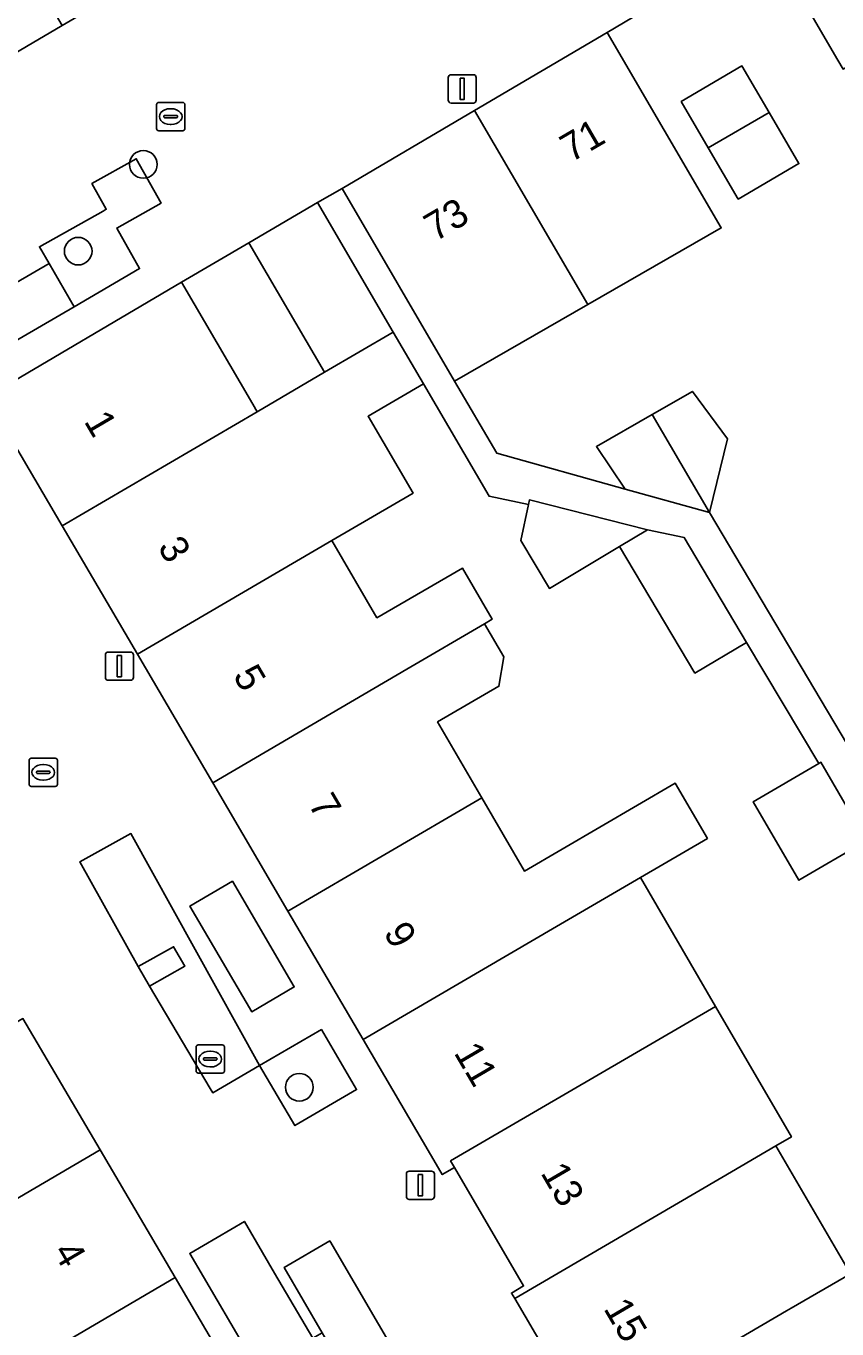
# Model space of a CAD drawing. Extents: x 161771 to 163125, y 382475 to 383179.
# Drawn here: x 162254.94 to 162283.63, y 382779.88 to 382825.98 of the extents above; entities that cross this region are included whole.
import ezdxf

# ---------------------------------------------------------------- set-up
doc = ezdxf.new("R2010")
doc.units = 0
for name, color, linetype in [('IMGEO_Boom', 7, 'Continuous'), ('IMGEO_Erf', 7, 'Continuous'), ('IMGEO_Groenvoorziening', 7, 'Continuous'), ('IMGEO_Kolk', 7, 'Continuous'), ('IMGEO_Lichtmast', 7, 'Continuous'), ('IMGEO_Muur', 7, 'Continuous'), ('IMGEO_Pand', 7, 'Continuous'), ('IMGEO_Pand_nummerreeks', 7, 'Continuous'), ('IMGEO_Parkeervlak_open', 7, 'Continuous'), ('IMGEO_Verkeerseiland_open', 7, 'Continuous'), ('IMGEO_Voetpad_open', 7, 'Continuous'), ('IMGEO_Woonerf_open', 7, 'Continuous')]:
    doc.layers.add(name, color=color, linetype=linetype)

msp = doc.modelspace()

# ---------------------------------------------------------------- linework, layer by layer
at = {"layer": 'IMGEO_Boom'}
for centre in [(162259.087, 382821.081), (162256.783, 382818.012), (162264.61, 382788.43)]:
    msp.add_circle(centre, 0.489, dxfattribs=at)
at = {"layer": 'IMGEO_Erf'}
for points in [[(162283.67, 382824.766), (162281.151, 382829.084), (162276.402, 382826.283), (162275.498, 382825.75), (162279.54, 382818.834), (162274.818, 382816.121), (162270.105, 382813.413), (162271.595, 382810.864), (162276.134, 382809.597), (162275.123, 382811.095), (162277.094, 382812.228), (162278.52, 382813.048), (162279.761, 382811.371), (162279.118, 382808.764), (162300.444, 382772.865)], [(162284.629, 382797.122), (162282.285, 382795.757), (162280.669, 382798.533), (162282.987, 382799.882), (162280.436, 382804.169), (162278.608, 382803.082), (162275.942, 382807.561), (162273.456, 382806.081), (162272.446, 382807.776), (162272.714, 382809.046), (162271.326, 382809.34), (162269.002, 382813.315), (162267.044, 382812.17), (162268.632, 382809.455), (162265.763, 382807.777), (162267.356, 382805.041), (162270.378, 382806.8), (162271.432, 382804.989), (162271.161, 382804.831), (162271.848, 382803.657), (162271.673, 382802.619), (162269.501, 382801.355), (162271.064, 382798.67), (162272.574, 382796.076), (162277.914, 382799.185), (162279.048, 382797.237), (162276.678, 382795.851), (162279.331, 382791.293), (162282.022, 382786.671), (162281.476, 382786.353), (162284.107, 382781.832)]]:
    msp.add_lwpolyline(points, dxfattribs=at)
for points in [[(162280.139, 382819.854), (162279.079, 382821.667), (162278.121, 382823.307), (162280.271, 382824.564), (162281.23, 382822.922), (162282.289, 382821.111)], [(162260.443, 382816.917), (162262.958, 382812.596), (162263.113, 382812.329), (162265.503, 382813.727), (162262.824, 382818.309)]]:
    msp.add_lwpolyline(points, close=True, dxfattribs=at)
at = {"layer": 'IMGEO_Groenvoorziening'}
for points in [[(162258.9, 382792.705), (162259.311, 382792.011), (162260.56, 382792.72), (162260.159, 382793.403)], [(162264.451, 382787.076), (162266.633, 382788.345), (162265.391, 382790.473), (162263.199, 382789.196)]]:
    msp.add_lwpolyline(points, close=True, dxfattribs=at)
at = {"layer": 'IMGEO_Kolk'}
for p, q in [((162259.558, 382822.347), (162259.558, 382823.199)), ((162259.633, 382823.273), (162260.485, 382823.273)), ((162260.559, 382823.199), (162260.559, 382822.347)), ((162259.817, 382822.767), (162259.817, 382822.779)), ((162260.255, 382822.73), (162259.857, 382822.73)), ((162259.86, 382822.816), (162260.258, 382822.816)), ((162260.046, 382823.053), (162260.071, 382823.053)), ((162260.301, 382822.779), (162260.301, 382822.767)), ((162260.485, 382822.273), (162259.633, 382822.273)), ((162260.069, 382822.493), (162260.044, 382822.493)), ((162255.121, 382800.072), (162255.973, 382800.072)), ((162255.046, 382799.146), (162255.046, 382799.998)), ((162255.305, 382799.566), (162255.305, 382799.578)), ((162255.348, 382799.615), (162255.746, 382799.615)), ((162255.534, 382799.852), (162255.559, 382799.852)), ((162255.789, 382799.578), (162255.789, 382799.566)), ((162256.047, 382799.998), (162256.047, 382799.146)), ((162255.743, 382799.529), (162255.345, 382799.529)), ((162255.557, 382799.292), (162255.532, 382799.292)), ((162255.973, 382799.072), (162255.121, 382799.072)), ((162261.031, 382789.929), (162261.883, 382789.929)), ((162260.956, 382789.003), (162260.956, 382789.855)), ((162261.215, 382789.423), (162261.215, 382789.435)), ((162261.258, 382789.472), (162261.656, 382789.472)), ((162261.444, 382789.709), (162261.469, 382789.709)), ((162261.699, 382789.435), (162261.699, 382789.423)), ((162261.957, 382789.855), (162261.957, 382789.003)), ((162261.653, 382789.386), (162261.255, 382789.386)), ((162261.467, 382789.149), (162261.442, 382789.149)), ((162261.883, 382788.929), (162261.031, 382788.929))]:
    msp.add_line(p, q, dxfattribs=at)
for points in [[(162259.558, 382822.347), (162259.558, 382823.199)], [(162259.633, 382823.273), (162260.485, 382823.273)], [(162260.559, 382823.199), (162260.559, 382822.347)], [(162260.485, 382822.273), (162259.633, 382822.273)], [(162255.121, 382800.072), (162255.973, 382800.072)], [(162255.046, 382799.146), (162255.046, 382799.998)], [(162256.047, 382799.998), (162256.047, 382799.146)], [(162255.973, 382799.072), (162255.121, 382799.072)], [(162261.031, 382789.929), (162261.883, 382789.929)], [(162260.956, 382789.003), (162260.956, 382789.855)], [(162261.957, 382789.855), (162261.957, 382789.003)], [(162261.883, 382788.929), (162261.031, 382788.929)]]:
    msp.add_lwpolyline(points, dxfattribs=at)
for centre, radius, start, end in [((162259.635, 382823.197), 0.0765, 91.552, 178.448), ((162259.635, 382823.197), 0.0765, 91.552, 178.448), ((162260.483, 382823.197), 0.0765, 1.552, 88.448), ((162260.483, 382823.197), 0.0765, 1.552, 88.448), ((162259.857, 382822.776), 0.0403, 85.8775, 175.7526), ((162259.854, 382822.766), 0.0366, 178.938, 274.7102), ((162260.258, 382822.773), 0.043, 264.8664, 352.4533), ((162260.262, 382822.778), 0.0386, 1.7309, 96.639), ((162259.635, 382822.349), 0.0765, 181.552, 268.448), ((162259.635, 382822.349), 0.0765, 181.552, 268.448), ((162260.483, 382822.349), 0.0765, 271.552, 358.448), ((162260.483, 382822.349), 0.0765, 271.552, 358.448), ((162255.123, 382799.996), 0.0765, 91.552, 178.448), ((162255.123, 382799.996), 0.0765, 91.552, 178.448), ((162255.971, 382799.996), 0.0765, 1.552, 88.448), ((162255.971, 382799.996), 0.0765, 1.552, 88.448), ((162255.345, 382799.575), 0.0403, 85.8775, 175.7526), ((162255.75, 382799.577), 0.0386, 1.7309, 96.639), ((162255.123, 382799.148), 0.0765, 181.552, 268.448), ((162255.123, 382799.148), 0.0765, 181.552, 268.448), ((162255.342, 382799.565), 0.0366, 178.938, 274.7102), ((162255.746, 382799.572), 0.043, 264.8664, 352.4533), ((162255.971, 382799.148), 0.0765, 271.552, 358.448), ((162255.971, 382799.148), 0.0765, 271.552, 358.448), ((162261.033, 382789.853), 0.0765, 91.552, 178.448), ((162261.033, 382789.853), 0.0765, 91.552, 178.448), ((162261.881, 382789.853), 0.0765, 1.552, 88.448), ((162261.881, 382789.853), 0.0765, 1.552, 88.448), ((162261.255, 382789.432), 0.0403, 85.8775, 175.7526), ((162261.66, 382789.434), 0.0386, 1.7309, 96.639), ((162261.033, 382789.005), 0.0765, 181.552, 268.448), ((162261.033, 382789.005), 0.0765, 181.552, 268.448), ((162261.252, 382789.422), 0.0366, 178.938, 274.7102), ((162261.656, 382789.429), 0.043, 264.8664, 352.4533), ((162261.881, 382789.005), 0.0765, 271.552, 358.448), ((162261.881, 382789.005), 0.0765, 271.552, 358.448)]:
    msp.add_arc(centre, radius, start, end, dxfattribs=at)
for centre, major_axis, ratio, start_param, end_param in [((162260.045, 382822.773), (-0.387, 0.002), 0.722429, 4.712389, 7.853982), ((162260.07, 382822.773), (-0.39, 0.002), 0.717154, 1.570796, 4.712389), ((162255.533, 382799.572), (-0.387, 0.002), 0.722429, 4.712389, 7.853982), ((162255.558, 382799.572), (-0.39, 0.002), 0.717154, 1.570796, 4.712389), ((162261.443, 382789.429), (-0.387, 0.002), 0.722429, 4.712389, 7.853982), ((162261.468, 382789.429), (-0.39, 0.002), 0.717154, 1.570796, 4.712389)]:
    msp.add_ellipse(centre, major_axis=major_axis, ratio=ratio, start_param=start_param, end_param=end_param, dxfattribs=at)
at = {"layer": 'IMGEO_Lichtmast'}
for p, q in [((162269.877, 382823.354), (162269.877, 382824.154)), ((162269.877, 382824.154), (162269.877, 382823.354)), ((162269.977, 382824.254), (162270.767, 382824.254)), ((162270.767, 382824.254), (162269.977, 382824.254)), ((162270.867, 382824.154), (162270.867, 382823.354)), ((162270.867, 382823.354), (162270.867, 382824.154)), ((162270.767, 382823.254), (162269.977, 382823.254)), ((162269.977, 382823.254), (162270.767, 382823.254)), ((162257.745, 382802.929), (162257.745, 382803.729)), ((162257.745, 382803.729), (162257.745, 382802.929)), ((162257.845, 382803.829), (162258.635, 382803.829)), ((162258.635, 382803.829), (162257.845, 382803.829)), ((162258.735, 382803.729), (162258.735, 382802.929)), ((162258.735, 382802.929), (162258.735, 382803.729)), ((162258.635, 382802.829), (162257.845, 382802.829)), ((162257.845, 382802.829), (162258.635, 382802.829)), ((162268.396, 382784.563), (162268.396, 382785.363)), ((162268.396, 382785.363), (162268.396, 382784.563)), ((162268.496, 382785.463), (162269.286, 382785.463)), ((162269.286, 382785.463), (162268.496, 382785.463)), ((162269.386, 382785.363), (162269.386, 382784.563)), ((162269.386, 382784.563), (162269.386, 382785.363)), ((162269.286, 382784.463), (162268.496, 382784.463)), ((162268.496, 382784.463), (162269.286, 382784.463))]:
    msp.add_line(p, q, dxfattribs=at)
for points in [[(162270.297, 382824.129), (162270.447, 382824.129), (162270.447, 382823.379), (162270.297, 382823.379), (162270.297, 382824.129)], [(162258.165, 382803.704), (162258.315, 382803.704), (162258.315, 382802.954), (162258.165, 382802.954), (162258.165, 382803.704)], [(162268.816, 382785.338), (162268.966, 382785.338), (162268.966, 382784.588), (162268.816, 382784.588), (162268.816, 382785.338)]]:
    msp.add_lwpolyline(points, dxfattribs=at)
for centre, start, end in [((162269.977, 382824.154), 90, 180), ((162269.977, 382824.154), 90, 180), ((162270.767, 382824.154), 0, 90), ((162270.767, 382824.154), 360, 90), ((162269.977, 382823.354), 180, 270), ((162269.977, 382823.354), 180, 270), ((162270.767, 382823.354), 270, 0), ((162270.767, 382823.354), 270, 0), ((162257.845, 382803.729), 90, 180), ((162257.845, 382803.729), 90, 180), ((162258.635, 382803.729), 0, 90), ((162258.635, 382803.729), 360, 90), ((162257.845, 382802.929), 180, 270), ((162257.845, 382802.929), 180, 270), ((162258.635, 382802.929), 270, 0), ((162258.635, 382802.929), 270, 0), ((162268.496, 382785.363), 90, 180), ((162268.496, 382785.363), 90, 180), ((162269.286, 382785.363), 0, 90), ((162269.286, 382785.363), 360, 90), ((162268.496, 382784.563), 180, 270), ((162268.496, 382784.563), 180, 270), ((162269.286, 382784.563), 270, 0), ((162269.286, 382784.563), 270, 0)]:
    msp.add_arc(centre, 0.1, start, end, dxfattribs=at)
at = {"layer": 'IMGEO_Muur'}
msp.add_lwpolyline([(162260.443, 382816.917), (162262.824, 382818.309)], dxfattribs=at)
at = {"layer": 'IMGEO_Pand'}
for points in [[(162252.159, 382832.923), (162252.016, 382833.167), (162250.262, 382832.14), (162249.493, 382833.452), (162246.824, 382838.005), (162246.064, 382837.559), (162244.977, 382836.922), (162244.758, 382836.794), (162245.431, 382835.65), (162252.42, 382823.768), (162256.216, 382825.999)], [(162290.767, 382828.488), (162288.055, 382833.13), (162281.151, 382829.084), (162283.67, 382824.766), (162283.853, 382824.453)], [(162274.818, 382816.121), (162279.54, 382818.834), (162275.498, 382825.75), (162270.803, 382822.988)], [(162281.23, 382822.922), (162280.271, 382824.564), (162278.121, 382823.307), (162279.079, 382821.667)], [(162274.818, 382816.121), (162270.803, 382822.988), (162266.119, 382820.233), (162270.105, 382813.413)], [(162281.23, 382822.922), (162279.079, 382821.667), (162280.139, 382819.854), (162282.289, 382821.111)], [(162265.503, 382813.727), (162267.931, 382815.147), (162265.251, 382819.732), (162262.824, 382818.309)], [(162256.216, 382808.295), (162263.113, 382812.329), (162262.958, 382812.596), (162260.443, 382816.917), (162253.545, 382812.855), (162254.568, 382811.108)], [(162256.216, 382808.295), (162258.879, 382803.75), (162265.763, 382807.777), (162268.632, 382809.455), (162267.044, 382812.17), (162269.002, 382813.315), (162267.931, 382815.147), (162265.503, 382813.727), (162263.113, 382812.329)], [(162277.094, 382812.228), (162279.118, 382808.764), (162279.761, 382811.371), (162278.52, 382813.048)], [(162277.094, 382812.228), (162275.123, 382811.095), (162276.134, 382809.597), (162279.118, 382808.764)], [(162276.933, 382808.151), (162272.749, 382809.212), (162272.714, 382809.046), (162272.446, 382807.776), (162273.456, 382806.081), (162275.942, 382807.561)], [(162280.436, 382804.169), (162278.23, 382807.876), (162276.933, 382808.151), (162275.942, 382807.561), (162278.608, 382803.082)], [(162271.161, 382804.831), (162271.432, 382804.989), (162270.378, 382806.8), (162267.356, 382805.041), (162265.763, 382807.777), (162258.879, 382803.75), (162261.542, 382799.205), (162268.414, 382803.224)], [(162264.205, 382794.659), (162271.064, 382798.67), (162269.501, 382801.355), (162271.673, 382802.619), (162271.848, 382803.657), (162271.161, 382804.831), (162268.414, 382803.224), (162261.542, 382799.205)], [(162282.987, 382799.882), (162280.669, 382798.533), (162282.285, 382795.757), (162284.629, 382797.122), (162284.684, 382797.154), (162283.068, 382799.929)], [(162276.678, 382795.851), (162279.048, 382797.237), (162277.914, 382799.185), (162272.574, 382796.076), (162271.064, 382798.67), (162264.205, 382794.659), (162266.867, 382790.114), (162273.714, 382794.118)], [(162279.331, 382791.293), (162276.678, 382795.851), (162273.714, 382794.118), (162266.867, 382790.114), (162269.53, 382785.568), (162269.664, 382785.34), (162270.097, 382785.59), (162269.962, 382785.821)], [(162281.476, 382786.353), (162282.022, 382786.671), (162279.331, 382791.293), (162269.962, 382785.821), (162270.097, 382785.59), (162272.547, 382781.399), (162272.114, 382781.149), (162272.229, 382780.952), (162279.563, 382785.24)], [(162250.409, 382782.028), (162257.56, 382786.216), (162254.83, 382790.861), (162250.517, 382788.334), (162247.679, 382786.671)], [(162250.409, 382782.028), (162253.067, 382777.508), (162260.217, 382781.695), (162257.56, 382786.216)], [(162284.107, 382781.832), (162281.476, 382786.353), (162279.563, 382785.24), (162272.229, 382780.952), (162274.871, 382776.438), (162281.844, 382780.515), (162282.009, 382780.611)], [(162287.275, 382777.626), (162287.485, 382777.748), (162284.854, 382782.267), (162284.107, 382781.832), (162282.009, 382780.611), (162281.844, 382780.515), (162274.871, 382776.438), (162277.513, 382771.923), (162284.64, 382776.092)], [(162260.217, 382781.695), (162253.067, 382777.508), (162255.725, 382772.988), (162262.873, 382777.174)]]:
    msp.add_lwpolyline(points, close=True, dxfattribs=at)
at = {"layer": 'IMGEO_Parkeervlak_open'}
for points in [[(162256.638, 382816.047), (162255.752, 382817.574), (162251.339, 382815.015), (162252.229, 382813.481)], [(162258.647, 382797.406), (162256.847, 382796.408), (162258.9, 382792.705), (162260.159, 382793.403), (162260.56, 382792.72), (162259.311, 382792.011), (162261.457, 382788.387), (162261.547, 382788.233), (162263.199, 382789.196)], [(162262.239, 382795.718), (162260.737, 382794.838), (162262.926, 382791.101), (162264.428, 382791.981)], [(162263.735, 382781.852), (162262.663, 382783.684), (162260.728, 382782.551), (162263.148, 382778.416), (162265.084, 382779.551)], [(162264.071, 382782.049), (162265.418, 382779.747), (162266.653, 382777.623), (162268.272, 382778.57), (162265.684, 382782.992)]]:
    msp.add_lwpolyline(points, close=True, dxfattribs=at)
at = {"layer": 'IMGEO_Verkeerseiland_open'}
msp.add_lwpolyline([(162257.775, 382819.493), (162257.668, 382819.433), (162255.409, 382818.166), (162255.752, 382817.574), (162256.638, 382816.047), (162258.953, 382817.394), (162258.147, 382818.831), (162259.717, 382819.712), (162258.836, 382821.281), (162257.266, 382820.401)], close=True, dxfattribs=at)
at = {"layer": 'IMGEO_Voetpad_open'}
msp.add_lwpolyline([(162300.444, 382772.865), (162279.118, 382808.764), (162276.134, 382809.597), (162271.595, 382810.864), (162270.105, 382813.413), (162266.119, 382820.233), (162265.251, 382819.732), (162267.931, 382815.147), (162269.002, 382813.315), (162271.326, 382809.34), (162272.714, 382809.046), (162272.749, 382809.212), (162276.933, 382808.151), (162278.23, 382807.876), (162280.436, 382804.169), (162282.987, 382799.882), (162283.068, 382799.929), (162284.684, 382797.154), (162284.629, 382797.122), (162289.568, 382788.823), (162306.253, 382760.786)], dxfattribs=at)
at = {"layer": 'IMGEO_Woonerf_open'}
for points in [[(162265.251, 382819.732), (162266.119, 382820.233), (162270.803, 382822.988), (162275.498, 382825.75), (162276.402, 382826.283), (162281.151, 382829.084), (162288.055, 382833.13), (162296.657, 382838.143), (162303.561, 382842.189), (162306.973, 382844.182), (162308.202, 382844.901), (162312.832, 382847.618), (162317.385, 382850.29), (162321.937, 382852.962), (162326.491, 382855.634), (162331.169, 382858.38)], [(162284.383, 382842.553), (162283.477, 382842.022), (162279.427, 382839.641), (162275.547, 382837.361), (162271.667, 382835.081), (162267.788, 382832.801), (162263.908, 382830.52), (162260.009, 382828.229), (162256.216, 382825.999), (162252.42, 382823.768), (162248.564, 382821.502), (162245.808, 382819.868), (162238.887, 382815.82), (162241.801, 382810.837), (162233.78, 382806.145), (162230.884, 382811.096), (162229.285, 382810.148), (162222.787, 382806.395)], [(162209.001, 382778.957), (162208.186, 382780.333), (162211.552, 382782.301), (162211.009, 382783.377), (162211.617, 382785.721), (162227.846, 382795.37), (162232.439, 382798.077), (162236.911, 382800.713), (162241.383, 382803.349), (162245.956, 382806.045), (162248.416, 382807.495), (162249.087, 382807.891), (162250.657, 382808.817), (162254.568, 382811.108), (162253.545, 382812.855), (162260.443, 382816.917), (162262.824, 382818.309), (162265.251, 382819.732)], [(162274.871, 382776.438), (162272.229, 382780.952), (162272.114, 382781.149), (162272.547, 382781.399), (162270.097, 382785.59), (162269.664, 382785.34), (162269.53, 382785.568), (162266.867, 382790.114), (162264.205, 382794.659), (162261.542, 382799.205), (162258.879, 382803.75), (162256.216, 382808.295), (162254.568, 382811.108)], [(162254.83, 382790.861), (162257.56, 382786.216), (162260.217, 382781.695), (162262.873, 382777.174)]]:
    msp.add_lwpolyline(points, dxfattribs=at)
for points in [[(162257.266, 382820.401), (162258.836, 382821.281), (162259.717, 382819.712), (162258.147, 382818.831), (162258.953, 382817.394), (162256.638, 382816.047), (162252.229, 382813.481), (162251.339, 382815.015), (162255.752, 382817.574), (162255.409, 382818.166), (162257.668, 382819.433), (162257.775, 382819.493)], [(162261.547, 382788.233), (162261.457, 382788.387), (162259.311, 382792.011), (162258.9, 382792.705), (162256.847, 382796.408), (162258.647, 382797.406), (162263.199, 382789.196)], [(162260.737, 382794.838), (162262.239, 382795.718), (162264.428, 382791.981), (162262.926, 382791.101)], [(162263.199, 382789.196), (162265.391, 382790.473), (162266.633, 382788.345), (162264.451, 382787.076)], [(162268.272, 382778.57), (162266.653, 382777.623), (162264.372, 382776.288), (162263.148, 382778.416), (162260.728, 382782.551), (162262.663, 382783.684), (162263.735, 382781.852), (162265.084, 382779.551), (162265.418, 382779.747), (162264.071, 382782.049), (162265.684, 382782.992)]]:
    msp.add_lwpolyline(points, close=True, dxfattribs=at)

# ---------------------------------------------------------------- texts
at = {"layer": 'IMGEO_Pand_nummerreeks'}
for s, rotation, p in [('71', 30.165, (162274.222, 382821.135)), ('73', 30.3791, (162269.412, 382818.331)), ('1', 300.3629, (162256.969, 382811.994)), ('3', 300.3629, (162259.577, 382807.544)), ('5', 300.3608, (162262.241, 382802.997)), ('7', 300.3629, (162264.905, 382798.449)), ('9', 300.3608, (162267.569, 382793.902)), ('11', 300.3608, (162270.058, 382789.652)), ('13', 300.3093, (162273.127, 382785.401)), ('4', 300.4413, (162255.873, 382782.612)), ('15', 300.3322, (162275.354, 382780.602))]:
    msp.add_text(s, height=1, rotation=rotation, dxfattribs=at).set_placement(p)

doc.saveas('drawing.dxf')
